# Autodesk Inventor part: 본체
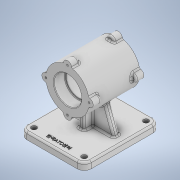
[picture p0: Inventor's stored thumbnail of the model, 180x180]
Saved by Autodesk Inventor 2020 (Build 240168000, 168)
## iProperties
Created: 2022-11
Part Number: 본체
Material: 일반
Document SubType Name: Modeling
Designer: owner
Density: 1 g/cm^3
Appearance: 기본값
Mass: 449.997 g
Surface Area: 797.002 cm^2
Volume: 449.997 cm^3
Author: owner
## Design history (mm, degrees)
sketch "스케치1"
  geometry: C1 r 37 at (0, 0); 1 further point
  constraints: 1 centre point, 1 coincident
  dimensions: "d0" = 74 diameter of C1
extrude "돌출1" new body sketch "스케치1" stored distance "d1" = 87; taper "d3" = 0 deg; dims "d2" = 5, "d4" = 0
node "작업 평면1"
sketch "스케치2"
  geometry: L1 (-37, -43.5)-(37, -43.5) reference; L2 (37, 43.5)-(-37, 43.5) reference; L3 (-55, -60)-(55, -60); L4 (55, -60)-(55, 70); L5 (55, 70)-(-55, 70); L6 (-55, 70)-(-55, -60); 2 further points
  constraints: 8 end point, 2 parallel, 1 horizontal, 1 midpoint, 1 perpendicular, 1 vertical alignment
  dimensions: "d6" = 130 distance of L5.end L3.start; "d7" = 110 distance of L4.end L5.end; "d9" = 70 distance of point (0, 0) point (0, 70)
extrude "돌출2" join sketch "스케치2" distance "d10" = 12; taper "d11" = 0 deg
sketch "스케치3"
  geometry: L1 (-55, -82)-(55, -82) reference; L2 (55, -82)-(55, -70) reference; L3 (-55, -70)-(55, -70) reference; L4 (-55, -82)-(-55, -70) reference; L5 (-55, -70)-(55, -70) reference; L6 (-41, -70)-(-25.336, -26.964); L7 (41, -70)-(25.336, -26.964); A1 r 37 centre (0, 0) between (-25.336, -26.964) and (25.336, -26.964) reference; 3 further points
  constraints: 4 end point, 2 point on circle, 2 point on line
  dimensions: "d12" = 110 deg angle of L3 L6; "d13" = 110 deg angle of L3 L7; "d14" = 14 distance from line of L4 L6.start; "d15" = 14 distance from line of L2 L7.start
extrude "돌출3" join sketch "스케치3" stored distance "d16" = 10; taper "d17" = 0 deg
sketch "스케치4"
  geometry: L1 (-82, 70)-(-82, -60) reference; L2 (-82, -60)-(-70, -60) reference; L3 (-70, 70)-(-70, -60) reference; L4 (-82, 70)-(-70, 70) reference; L5 (-26.964, 5)-(-26.964, -5) reference; L6 (-70, 5)-(-26.964, 5) reference; L7 (-70, -5)-(-70, 5) reference; L8 (-26.964, -5)-(-70, -5) reference; L9 (-70, -60)-(-70, 70) reference; L10 (-70, 20)-(-34.867, 20); 2 further points
  constraints: 2 end point, 2 point on line, 1 perpendicular
  dimensions: "d18" = 20 distance of point (-70, 0) L10.start
feature "리브1" sketch "스케치4" dims "d19" = 1, "d20" = 10, "d21" = 0, "d22" = 0, "d23" = 1, "d24" = 1
sketch "스케치5"
  geometry: C1 r 37 at (0, 0) reference; 2 further points
  constraints: 1 coincident
hole "구멍1" sketch "스케치5" at (0, 0) diameter "d25" = 42; stored, may be unused: countersink angle "d29" = 90 deg, drill point angle "d31" = 118 deg; dims "d26" = 8, "d27" = 47, "d28" = 19, "d30" = 10
sketch "스케치6"
  geometry: C1 r 37 at (0, 0) reference; 2 further points
  constraints: 1 coincident
hole "구멍2" sketch "스케치6" at (0, 0) diameter "d32" = 47; stored, may be unused: countersink angle "d36" = 90 deg, drill point angle "d38" = 0 deg; dims "d33" = 8, "d34" = 47, "d35" = 19, "d37" = 19
sketch "스케치7"
  geometry: C1 r 7 at (0, 37); 4 further points
  constraints: 1 centre point, 1 vertical alignment, 2 other
  dimensions: "d39" = 14 diameter of C1
extrude "돌출4" join sketch "스케치7" distance "d40" = 14; taper "d41" = 0 deg
sketch "스케치9"
  geometry: A1 r 7 centre (0, 37) between (6.969, 36.338) and (-6.969, 36.338) reference; 2 further points
  constraints: 1 coincident
hole "구멍3" sketch "스케치9" at (0, 37) diameter "d45" = 3.242; stored, may be unused: countersink angle "d49" = 90 deg, drill point angle "d51" = 118 deg; dims "d46" = 8, "d47" = 47, "d48" = 19, "d50" = 10
fillet "모깎기1" dims "d55" = 3
fillet "모깎기2" dims "d56" = 3
fillet "모깎기3" dims "d60" = 12
sketch "스케치10"
  geometry: A1 r 12 centre (-43, -58) between (-55, -58) and (-43, -70) reference; A2 r 12 centre (43, -58) between (43, -70) and (55, -58) reference; A3 r 12 centre (43, 48) between (55, 48) and (43, 60) reference; A4 r 12 centre (-43, 48) between (-43, 60) and (-55, 48) reference; 5 further points
  constraints: 4 coincident
hole "구멍4" sketch "스케치10" at (-43, -58), (43, -58), (43, 48), (-43, 48) diameter "d61" = 9; stored, may be unused: countersink angle "d65" = 90 deg, drill point angle "d67" = 118 deg; dims "d62" = 8, "d63" = 47, "d64" = 19, "d66" = 10
fillet "모깎기4" dims "d68" = 3
fillet "모깎기5" dims "d69" = 1
fillet "모깎기6" dims "d70" = 3
fillet "모깎기7" dims "d71" = 3
chamfer "모따기1" distance "d72" = 1; stored, may be unused: second distance "d73" = 2, angle "d74" = 45 deg
sketch "스케치11"
  geometry: L1 (-43, -70)-(43, -70) reference; 3 further points
  constraints: 1 midpoint, 1 vertical alignment, 1 other
  dimensions: "d75" = 12 distance from line of L1 point (0, -58)
feature "엠보싱1" sketch "스케치11" dims "d1" = 87, "d3" = 0, "d76" = 0.5, "d77" = 0
node "솔리드1"
mirror "미러1"
pattern_circular "원형 패턴3" dims "d58" = 360 deg
mirror "미러2"
node "투영된 루프1"
node "투영된 루프2"
node "투영된 루프3"
node "투영된 루프4"
node "투영된 루프5"
feature "A9D066F2-1C7D-4E18-AEED-F7BC21143FA4" dims "d25" = 42, "d26" = 8, "d27" = 47, "d28" = 19, "d29" = 90 deg, "d30" = 10, "d31" = 118 deg
other parameters: "d5" = -82
